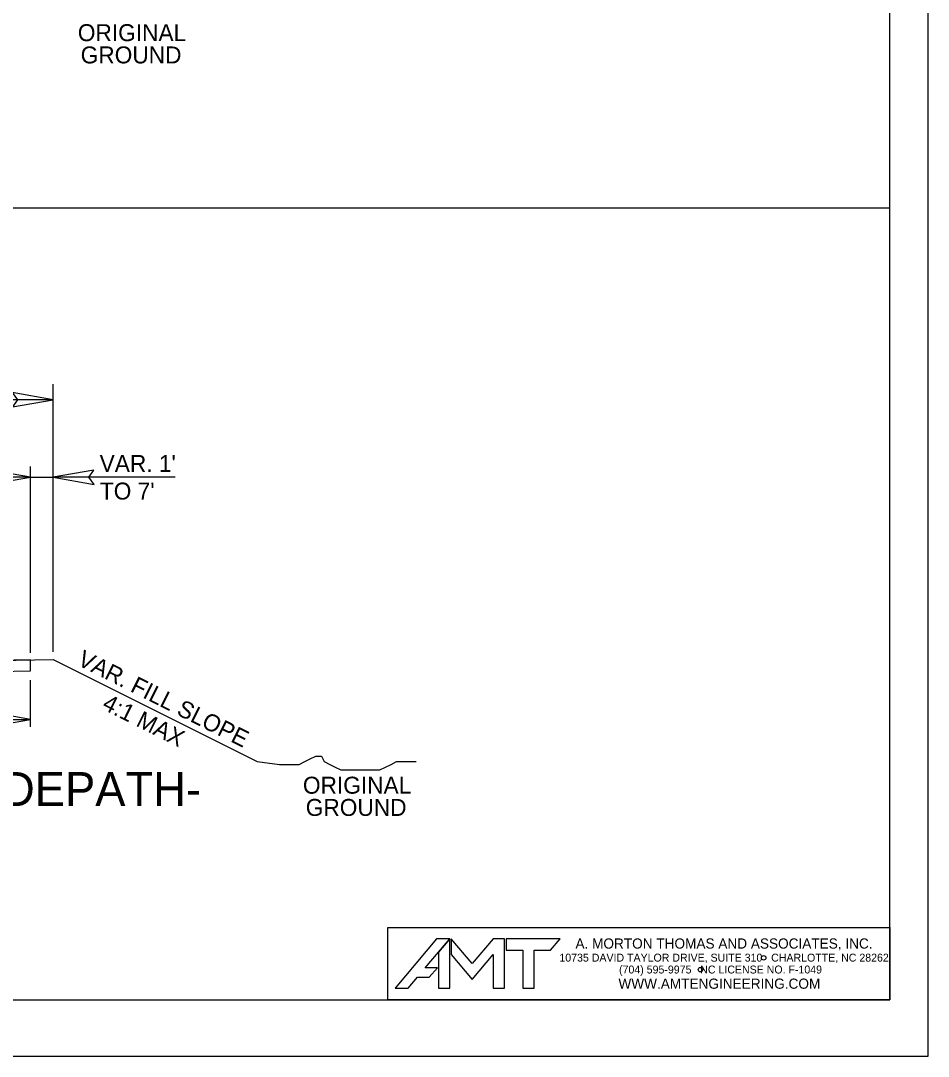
# Model space of a CAD drawing. Extents: x 1487909 to 1489267, y 497866 to 499814.
# Drawn here: x 1489011.53 to 1489051.66, y 498227.52 to 498273.3 of the extents above; entities that cross this region are included whole.
import ezdxf

# ---------------------------------------------------------------- set-up
doc = ezdxf.new("R2010")
doc.units = 0
for name, color, linetype in [('Prop Conc 4in Sidewalk', 7, 'Continuous'), ('Prop Dimension', 7, 'Continuous'), ('Prop Dimension Text', 7, 'Continuous'), ('Prop Grid Mask', 7, 'Continuous'), ('Prop Shade Light', 7, 'Continuous'), ('Prop Terminator CELL', 7, 'Continuous'), ('Scratch_Level_1', 7, 'Continuous'), ('Sheet Block Title CELL', 7, 'Continuous'), ('Sheet Plot Border Outside CELL', 7, 'Continuous'), ('Sheet Typical CELL', 7, 'Continuous'), ('Typical Hinge Slope Arterial CELL', 7, 'Continuous'), ('Typical Hinge Slope Interstate CELL', 7, 'Continuous'), ('Typical Pavement Slope CELL', 7, 'Continuous')]:
    doc.layers.add(name, color=color, linetype=linetype)

msp = doc.modelspace()

# ---------------------------------------------------------------- linework, layer by layer
at = {"layer": 'Prop Conc 4in Sidewalk'}
for p, q in [((1489001.963, 498244.839), (1489011.963, 498245.039)), ((1489011.963, 498244.558), (1489011.963, 498245.039)), ((1489001.963, 498244.358), (1489011.963, 498244.558))]:
    msp.add_line(p, q, dxfattribs=at)
at = {"layer": 'Prop Dimension'}
for p, q in [((1489012.964, 498245.404), (1489012.964, 498257.235)), ((1489012.964, 498256.545), (1488993.464, 498256.545)), ((1489011.964, 498245.361), (1489011.964, 498253.586)), ((1489011.964, 498253.115), (1489001.964, 498253.115)), ((1489011.964, 498253.115), (1489012.964, 498253.115)), ((1489018.355, 498253.115), (1489012.964, 498253.115)), ((1489011.963, 498242.087), (1489011.963, 498244.144)), ((1489006.963, 498242.407), (1489011.963, 498242.407))]:
    msp.add_line(p, q, dxfattribs=at)
at = {"layer": 'Prop Grid Mask'}
msp.add_lwpolyline([(1489027.76, 498233.215), (1489049.964, 498233.215), (1489049.964, 498230.02), (1489027.76, 498230.02)], close=True, dxfattribs=at)
at = {"layer": 'Prop Shade Light'}
for p, q in [((1489011.963, 498245.039), (1489001.963, 498244.839)), ((1489011.963, 498244.558), (1489011.963, 498245.039)), ((1489001.963, 498244.358), (1489011.963, 498244.558))]:
    msp.add_line(p, q, dxfattribs=at)
at = {"layer": 'Prop Terminator CELL'}
for points in [[(1489011.164, 498256.235), (1489012.964, 498256.545), (1489011.154, 498256.865), (1489011.384, 498256.545)], [(1489010.164, 498252.805), (1489011.964, 498253.115), (1489010.154, 498253.435), (1489010.384, 498253.115)], [(1489014.764, 498253.425), (1489012.964, 498253.115), (1489014.774, 498252.795), (1489014.544, 498253.115)], [(1489010.163, 498242.097), (1489011.963, 498242.407), (1489010.153, 498242.727), (1489010.383, 498242.407)]]:
    msp.add_lwpolyline(points, close=True, dxfattribs=at)
at = {"layer": 'Scratch_Level_1'}
msp.add_line((1488899.964, 498265.02), (1489049.964, 498265.02), dxfattribs=at)
at = {"layer": 'Sheet Block Title CELL'}
msp.add_lwpolyline([(1489027.76, 498233.215), (1489049.964, 498233.215), (1489049.964, 498230.02), (1489027.76, 498230.02)], close=True, dxfattribs=at)
for points in [[(1489030.002, 498232.129), (1489030.506, 498232.719), (1489029.918, 498232.719), (1489028.095, 498230.524), (1489028.665, 498230.524), (1489029.074, 498231.018), (1489029.596, 498231.018), (1489029.954, 498231.432), (1489029.414, 498231.432), (1489030.002, 498232.129)], [(1489030.506, 498230.524), (1489030.506, 498232.719), (1489030.002, 498232.129), (1489030.002, 498230.524), (1489030.506, 498230.524)], [(1489031.493, 498230.911), (1489032.425, 498232.023), (1489032.425, 498230.524), (1489032.929, 498230.524), (1489032.929, 498232.719), (1489032.425, 498232.719), (1489031.493, 498231.624), (1489030.571, 498232.719), (1489030.571, 498232.021), (1489031.493, 498230.911)], [(1489034.232, 498230.524), (1489034.232, 498232.216), (1489034.961, 498232.216), (1489035.382, 498232.719), (1489032.993, 498232.719), (1489032.993, 498232.216), (1489033.729, 498232.216), (1489033.729, 498230.524), (1489034.232, 498230.524)]]:
    msp.add_lwpolyline(points, dxfattribs=at)
for centre in [(1489044.382, 498231.872), (1489041.591, 498231.35)]:
    msp.add_circle(centre, 0.1, dxfattribs=at)
at = {"layer": 'Sheet Plot Border Outside CELL'}
msp.add_lwpolyline([(1489051.664, 498337.52), (1488883.264, 498337.52), (1488883.264, 498227.52), (1489051.664, 498227.52)], close=True, dxfattribs=at)
at = {"layer": 'Sheet Typical CELL'}
msp.add_lwpolyline([(1489049.964, 498335.02), (1488899.964, 498335.02), (1488899.964, 498230.02), (1489049.964, 498230.02)], close=True, dxfattribs=at)
at = {"layer": 'Typical Hinge Slope Arterial CELL'}
msp.add_line((1489012.963, 498245.059), (1489021.992, 498240.545), dxfattribs=at)
msp.add_lwpolyline([(1489021.992, 498240.545), (1489022.978, 498240.422), (1489023.224, 498240.422), (1489023.594, 498240.422), (1489023.841, 498240.422), (1489024.087, 498240.545), (1489024.333, 498240.668), (1489024.58, 498240.792), (1489024.826, 498240.792), (1489024.95, 498240.545), (1489025.196, 498240.422), (1489025.443, 498240.298), (1489025.689, 498240.176), (1489025.935, 498240.176), (1489026.182, 498240.176), (1489026.428, 498240.176), (1489026.674, 498240.176), (1489026.921, 498240.176), (1489027.167, 498240.176), (1489027.414, 498240.176), (1489027.66, 498240.298), (1489027.906, 498240.422), (1489028.153, 498240.545), (1489028.523, 498240.545), (1489028.769, 498240.545), (1489029.015, 498240.545)], dxfattribs=at)
at = {"layer": 'Typical Pavement Slope CELL'}
msp.add_line((1488993.963, 498244.679), (1489012.963, 498245.059), dxfattribs=at)

# ---------------------------------------------------------------- texts
at = {"layer": 'Prop Dimension Text'}
for s, p in [("VAR. 1'", (1489015.021, 498253.349)), ("TO 7'", (1489015.031, 498252.13))]:
    msp.add_text(s, height=0.75, dxfattribs=at).set_placement(p)
at = {"layer": 'Sheet Block Title CELL'}
for s, height, p in [('A. MORTON THOMAS AND ASSOCIATES, INC.', 0.45, (1489036.061, 498232.28)), ('10735 DAVID TAYLOR DRIVE, SUITE 310   CHARLOTTE, NC 28262', 0.35, (1489035.351, 498231.705)), ('(704) 595-9975   NC LICENSE NO. F-1049', 0.35, (1489037.989, 498231.18)), ('WWW.AMTENGINEERING.COM', 0.45, (1489037.963, 498230.505))]:
    msp.add_text(s, height=height, rotation=359.9995, dxfattribs=at).set_placement(p)
at = {"layer": 'Typical Hinge Slope Arterial CELL'}
for s, p in [('ORIGINAL', (1489014.056, 498272.393)), ('GROUND', (1489014.182, 498271.409)), ('ORIGINAL', (1489024.009, 498239.128)), ('GROUND', (1489024.135, 498238.145))]:
    msp.add_text(s, height=0.75, dxfattribs=at).set_placement(p)
for s, p in [('VAR. FILL SLOPE', (1489013.989, 498244.836)), ('4:1 MAX', (1489015.086, 498242.891))]:
    msp.add_text(s, height=0.75, rotation=333.4658, dxfattribs=at).set_placement(p)
at = {"layer": 'Typical Hinge Slope Interstate CELL'}
msp.add_text('C -SIDEPATH-', height=1.5, dxfattribs=at).set_placement((1489006.133, 498238.584))

doc.saveas('drawing.dxf')
